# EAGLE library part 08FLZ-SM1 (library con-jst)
CONNECTOR
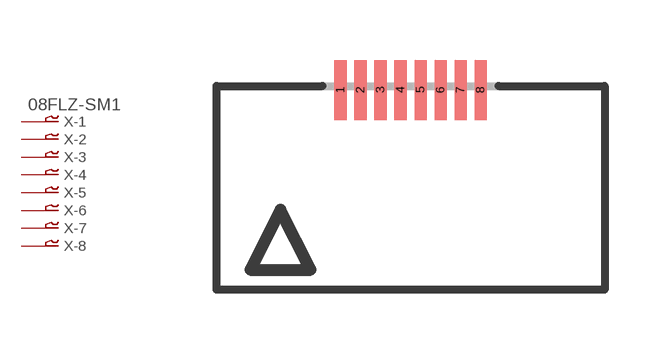
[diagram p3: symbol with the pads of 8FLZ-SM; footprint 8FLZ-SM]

Designator prefix X; gates -1=P-VN -2=P-N -3=P-N -4=P-N -5=P-N -6=P-N -7=P-N -8=P-N

## 08FLZ-SM1 (OC_FARNELL: unknown; OC_NEWARK: unknown)  [8FLZ-SM]
1  -1:1  pas
2  -2:1  pas
3  -3:1  pas
4  -4:1  pas
5  -5:1  pas
6  -6:1  pas
7  -7:1  pas
8  -8:1  pas

## Footprint 8FLZ-SM (pad centres in mm)
CONNECTOR
smd 0.3 x 1.5: 1 -1.75,2.5; 2 -1.25,2.5; 3 -0.75,2.5; 4 -0.25,2.5; 5 0.25,2.5; 6 0.75,2.5; 7 1.25,2.5; 8 1.75,2.5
